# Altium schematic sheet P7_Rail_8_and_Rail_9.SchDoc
size 368 x 228 mm
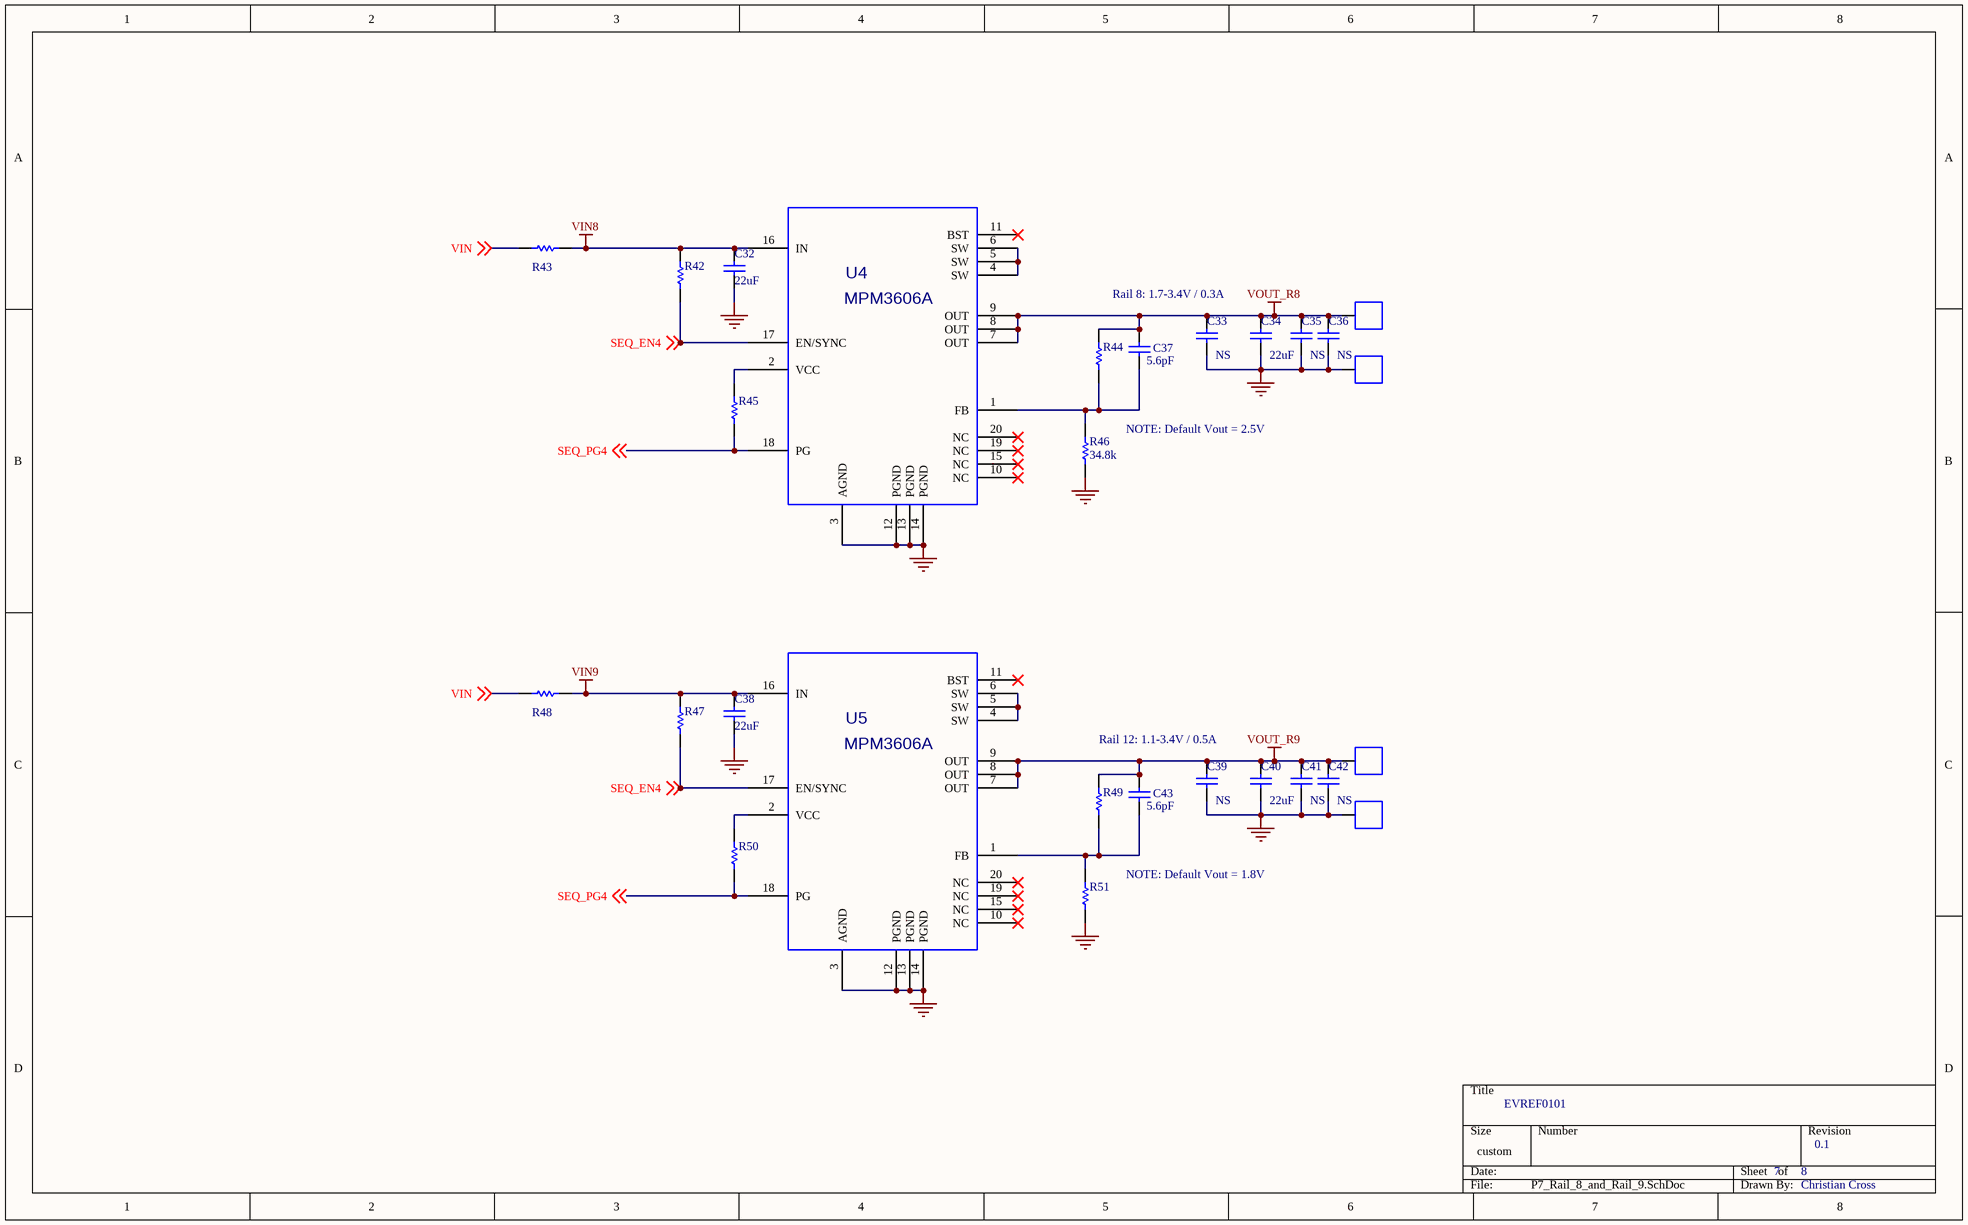
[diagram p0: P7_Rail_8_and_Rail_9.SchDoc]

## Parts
C32  22uF  [CAP0805]
C33  NS  [CAP0805]
C34  22uF  [CAP0805]
C35  NS  [CAP0805]
C36  NS  [CAP0805]
C37  5.6pF  [CAP/0603]
C38  22uF  [CAP0805]
C39  NS  [CAP0805]
C40  22uF  [CAP0805]
C41  NS  [CAP0805]
C42  NS  [CAP0805]
C43  5.6pF  [CAP/0603]
CN5  *  [TP2MM]  (value not drawn)
CN6  *  [TP2MM]  (value not drawn)
CN7  *  [TP2MM]  (value not drawn)
CN8  *  [TP2MM]  (value not drawn)
R42  NS  [RES/0603]  (value not drawn)
R43  10mohm  [RES/0805]  (value not drawn)
R44  75k  [RES/0603]  (value not drawn)
R45  NS  [RES/0603]  (value not drawn)
R46  34.8k  [RES/0603]
R47  NS  [RES/0603]  (value not drawn)
R48  10mohm  [RES/0805]  (value not drawn)
R49  102K  [RES/0603]  (value not drawn)
R50  NS  [RES/0603]  (value not drawn)
R51  82K  [RES/0603]  (value not drawn)
U4  MPM3606A  [QFN20-3X5MM]
U5  MPM3606A  [QFN20-3X5MM]

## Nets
GND: C32.1 C33.1 C34.1 C35.1 C36.1 C38.1 C39.1 C40.1 C41.1 C42.1 CN6.1 CN8.1 R46.2 R51.2 U4.3(AGND) U4.12(PGND) U4.13(PGND) U4.14(PGND) U5.3(AGND) U5.12(PGND) U5.13(PGND) U5.14(PGND)
VIN8: C32.2 R42.1 R43.2 U4.16(IN)
VIN9: C38.2 R47.1 R48.2 U5.16(IN)
VOUT_R8: C33.2 C34.2 C35.2 C36.2 C37.2 CN5.1 R44.1 U4.7(OUT) U4.8(OUT) U4.9(OUT)
VOUT_R9: C39.2 C40.2 C41.2 C42.2 C43.2 CN7.1 R49.1 U5.7(OUT) U5.8(OUT) U5.9(OUT)
SEQ_EN4: R42.2 R47.2 U4.17(EN/SYNC) U5.17(EN/SYNC) ; off-sheet SEQ_EN4
SEQ_PG4: R45.2 R50.2 U4.18(PG) U5.18(PG) ; off-sheet SEQ_PG4
VIN: R43.1 R48.1 ; off-sheet VIN
NetC37_1: C37.1 R44.2 R46.1 U4.1(FB)
NetC43_1: C43.1 R49.2 R51.1 U5.1(FB)
NetR45_1: R45.1 U4.2(VCC)
NetR50_1: R50.1 U5.2(VCC)
NetU4_4: U4.4(SW) U4.5(SW) U4.6(SW)
NetU5_4: U5.4(SW) U5.5(SW) U5.6(SW)

Not connected (* = marked no-connect by the designer): U4 10(NC)* 11(BST)* 15(NC)* 19(NC)* 20(NC)*; U5 10(NC)* 11(BST)* 15(NC)* 19(NC)* 20(NC)*

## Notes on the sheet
- Rail 8: 1.7-3.4V / 0.3A
- NOTE: Default Vout = 2.5V
- Rail 12: 1.1-3.4V / 0.5A
- NOTE: Default Vout = 1.8V
- EVREF0101
- 7
- 8
- 0.1
- Christian Cross

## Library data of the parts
C32-C43 = Cap: Capacitor
CN5-CN8 = TP2MM: {Description}; Manufacturer: {Manufacturer}; Manufacturer P/N: {Manufacturer P/N}
R42-R51 = Res1: Resistor
U4 U5 = MPM3630A: 18V/3A DC/DC Module Synchronous Step-Down Regulator; Manufacturer: {Manufacturer}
